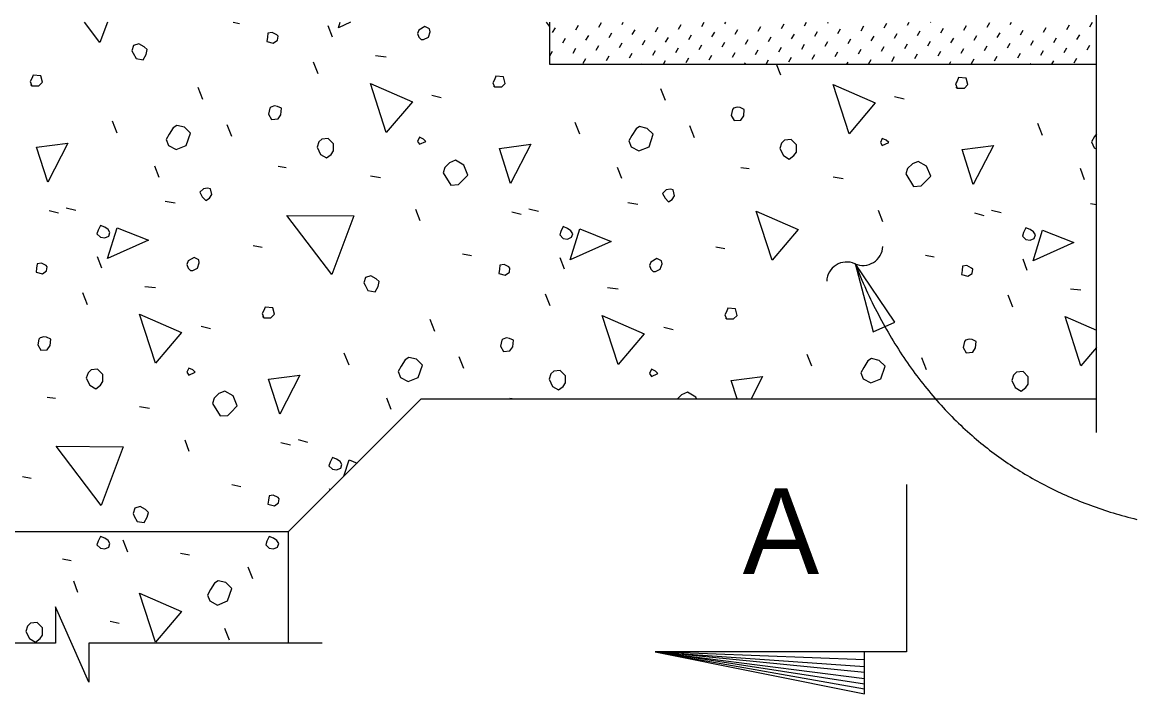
# Model space of a CAD drawing. Extents: x 120631.6 to 120706.2, y 120663.5 to 120716.4.
# Drawn here: x 120650.787 to 120654.117, y 120692.541 to 120694.546 of the extents above; entities that cross this region are included whole.
import ezdxf

# ---------------------------------------------------------------- set-up
doc = ezdxf.new("R2010")
doc.units = 0
for name, color, linetype in [('Dimension', 7, 'Continuous'), ('Miscellaneous', 7, 'Continuous'), ('TextStructures', 7, 'Continuous'), ('TrafBarrierConc', 7, 'Continuous')]:
    doc.layers.add(name, color=color, linetype=linetype)

msp = doc.modelspace()

# ---------------------------------------------------------------- linework, layer by layer
at = {"layer": 'Dimension'}
for p, q in [((120653.3036, 120692.6422), (120652.6786, 120692.6655)), ((120652.6786, 120692.6655), (120653.3036, 120692.6222)), ((120653.3036, 120692.6039), (120652.6786, 120692.6655)), ((120652.6786, 120692.6655), (120653.3036, 120692.5855)), ((120653.3036, 120692.5689), (120652.6786, 120692.6655)), ((120652.6786, 120692.6655), (120653.3036, 120692.5555))]:
    msp.add_line(p, q, dxfattribs=at)
for points in [[(120653.9962, 120693.3211), (120653.9962, 120695.4418), (120653.8928, 120695.4418), (120653.9962, 120695.4868), (120654.0995, 120695.5318), (120653.9962, 120695.5318), (120653.9962, 120696.2127)], [(120653.4286, 120693.1655), (120653.4286, 120692.6655), (120652.6786, 120692.6655), (120653.3036, 120692.5405), (120653.3036, 120692.6655)], [(120651.6828, 120692.6914), (120650.9858, 120692.6914), (120650.9858, 120692.5751), (120650.8864, 120692.8001), (120650.8864, 120692.6914), (120650.2312, 120692.6914)]]:
    msp.add_lwpolyline(points, dxfattribs=at)
msp.add_lwpolyline([(120653.2752, 120693.8252), (120653.3295, 120693.6211), (120653.3937, 120693.6504)], close=True, dxfattribs=at)
for centre, start, end in [((120653.2989, 120693.8792), 245.9128, 357.64), ((120653.2502, 120693.7704), 65.9128, 177.64)]:
    msp.add_arc(centre, 0.0596, start, end, dxfattribs=at)
msp.add_open_spline([(120653.2752, 120693.8251), (120653.5209, 120693.209), (120654.1168, 120693.0611)], degree=2, dxfattribs=at)
at = {"layer": 'Miscellaneous'}
for p, q in [((120651.417, 120694.546), (120651.4365, 120694.5421)), ((120651.7141, 120694.5015), (120651.7017, 120694.535)), ((120652.3718, 120694.5154), (120652.3799, 120694.5294)), ((120652.441, 120694.5235), (120652.4491, 120694.5375)), ((120652.5102, 120694.5316), (120652.5183, 120694.5456)), ((120652.5407, 120694.501), (120652.5488, 120694.515)), ((120652.5793, 120694.5397), (120652.583, 120694.546)), ((120652.6099, 120694.5091), (120652.618, 120694.5231)), ((120652.679, 120694.5172), (120652.6871, 120694.5312)), ((120652.7482, 120694.5253), (120652.7563, 120694.5393)), ((120652.8173, 120694.5334), (120652.8246, 120694.546)), ((120652.8479, 120694.5029), (120652.856, 120694.5169)), ((120652.8865, 120694.5415), (120652.8891, 120694.546)), ((120652.917, 120694.511), (120652.9251, 120694.525)), ((120652.9862, 120694.5191), (120652.9943, 120694.5331)), ((120653.0554, 120694.5272), (120653.0635, 120694.5412)), ((120653.1245, 120694.5353), (120653.1307, 120694.546)), ((120653.1551, 120694.5048), (120653.1632, 120694.5188)), ((120653.1937, 120694.5434), (120653.1952, 120694.546)), ((120653.2242, 120694.5129), (120653.2323, 120694.5269)), ((120653.2934, 120694.521), (120653.3015, 120694.535)), ((120653.3626, 120694.5291), (120653.3707, 120694.5431)), ((120653.4317, 120694.5372), (120653.4368, 120694.546)), ((120653.4622, 120694.5067), (120653.4703, 120694.5207)), ((120653.5009, 120694.5453), (120653.5013, 120694.546)), ((120653.5314, 120694.5148), (120653.5395, 120694.5288)), ((120653.6006, 120694.5229), (120653.6087, 120694.5369)), ((120653.6697, 120694.531), (120653.6778, 120694.545)), ((120653.7003, 120694.5004), (120653.7084, 120694.5144)), ((120653.7389, 120694.5391), (120653.7429, 120694.546)), ((120653.7694, 120694.5085), (120653.7775, 120694.5225)), ((120653.8386, 120694.5166), (120653.8467, 120694.5306)), ((120653.9078, 120694.5248), (120653.9159, 120694.5387)), ((120653.9769, 120694.5329), (120653.9845, 120694.546)), ((120652.4024, 120694.4848), (120652.4105, 120694.4988)), ((120652.4715, 120694.4929), (120652.4796, 120694.5069)), ((120652.5712, 120694.4705), (120652.5793, 120694.4845)), ((120652.6404, 120694.4786), (120652.6485, 120694.4926)), ((120652.7095, 120694.4867), (120652.7176, 120694.5007)), ((120652.7787, 120694.4948), (120652.7868, 120694.5088)), ((120652.8784, 120694.4724), (120652.8865, 120694.4864)), ((120652.9476, 120694.4805), (120652.9557, 120694.4945)), ((120653.0167, 120694.4886), (120653.0248, 120694.5026)), ((120653.0859, 120694.4967), (120653.094, 120694.5107)), ((120653.1856, 120694.4743), (120653.1937, 120694.4883)), ((120653.2548, 120694.4824), (120653.2629, 120694.4964)), ((120653.3239, 120694.4905), (120653.332, 120694.5045)), ((120653.3931, 120694.4986), (120653.4012, 120694.5126)), ((120653.4236, 120694.468), (120653.4317, 120694.482)), ((120653.4928, 120694.4761), (120653.5009, 120694.4901)), ((120653.5619, 120694.4842), (120653.57, 120694.4982)), ((120653.6311, 120694.4923), (120653.6392, 120694.5063)), ((120653.7308, 120694.4699), (120653.7389, 120694.4839)), ((120653.8, 120694.478), (120653.8081, 120694.492)), ((120653.8691, 120694.4861), (120653.8772, 120694.5001)), ((120653.9383, 120694.4942), (120653.9464, 120694.5082)), ((120652.3637, 120694.4462), (120652.3718, 120694.4602)), ((120652.4329, 120694.4543), (120652.441, 120694.4683)), ((120652.5021, 120694.4624), (120652.5102, 120694.4764)), ((120652.6017, 120694.44), (120652.6099, 120694.454)), ((120652.6709, 120694.4481), (120652.679, 120694.4621)), ((120652.7401, 120694.4562), (120652.7482, 120694.4702)), ((120652.8092, 120694.4643), (120652.8173, 120694.4783)), ((120652.8398, 120694.4337), (120652.8479, 120694.4477)), ((120652.9089, 120694.4419), (120652.917, 120694.4558)), ((120652.9781, 120694.45), (120652.9862, 120694.4639)), ((120653.0473, 120694.4581), (120653.0554, 120694.4721)), ((120653.1164, 120694.4662), (120653.1245, 120694.4802)), ((120653.147, 120694.4356), (120653.1551, 120694.4496)), ((120653.2161, 120694.4437), (120653.2242, 120694.4577)), ((120653.2853, 120694.4518), (120653.2934, 120694.4658)), ((120653.3544, 120694.4599), (120653.3626, 120694.4739)), ((120653.4541, 120694.4375), (120653.4622, 120694.4515)), ((120653.5233, 120694.4456), (120653.5314, 120694.4596)), ((120653.5925, 120694.4537), (120653.6006, 120694.4677)), ((120653.6616, 120694.4618), (120653.6697, 120694.4758)), ((120653.7613, 120694.4394), (120653.7694, 120694.4534)), ((120653.8305, 120694.4475), (120653.8386, 120694.4615)), ((120653.8997, 120694.4556), (120653.9078, 120694.4696)), ((120653.9688, 120694.4637), (120653.9769, 120694.4777)), ((120651.6717, 120694.3918), (120651.6575, 120694.4272)), ((120651.8431, 120694.4466), (120651.8749, 120694.4431)), ((120652.4634, 120694.4238), (120652.4715, 120694.4378)), ((120652.5326, 120694.4319), (120652.5407, 120694.4459)), ((120652.639, 120694.421), (120652.6404, 120694.4234)), ((120652.7034, 120694.421), (120652.7095, 120694.4315)), ((120652.7706, 120694.4256), (120652.7787, 120694.4396)), ((120652.9451, 120694.421), (120652.9476, 120694.4253)), ((120653.0095, 120694.421), (120653.0167, 120694.4334)), ((120653.054, 120694.3883), (120653.041, 120694.421)), ((120653.0778, 120694.4275), (120653.0859, 120694.4415)), ((120653.2512, 120694.421), (120653.2548, 120694.4272)), ((120653.3158, 120694.4213), (120653.3239, 120694.4353)), ((120653.385, 120694.4294), (120653.3931, 120694.4434)), ((120653.5573, 120694.421), (120653.5619, 120694.4291)), ((120653.623, 120694.4232), (120653.6311, 120694.4372)), ((120653.6922, 120694.4313), (120653.7003, 120694.4453)), ((120653.7989, 120694.421), (120653.8, 120694.4228)), ((120653.8634, 120694.421), (120653.8691, 120694.431)), ((120653.9302, 120694.4251), (120653.9383, 120694.4391)), ((120651.3269, 120694.3158), (120651.3128, 120694.3512)), ((120652.7093, 120694.3123), (120652.6952, 120694.3477)), ((120652.0111, 120694.3282), (120652.0393, 120694.3211)), ((120653.3935, 120694.3247), (120653.4217, 120694.3176)), ((120651.0706, 120694.2151), (120651.0565, 120694.2504)), ((120651.4136, 120694.2045), (120651.3994, 120694.2398)), ((120652.453, 120694.2115), (120652.4389, 120694.2469)), ((120652.796, 120694.2009), (120652.7818, 120694.2363)), ((120653.8354, 120694.208), (120653.8213, 120694.2434)), ((120651.1961, 120694.0825), (120651.1837, 120694.1161)), ((120651.5514, 120694.1161), (120651.5762, 120694.1125)), ((120651.8272, 120694.0878), (120651.8573, 120694.0825)), ((120652.5785, 120694.079), (120652.5661, 120694.1125)), ((120652.9338, 120694.1125), (120652.9586, 120694.109)), ((120653.2096, 120694.0843), (120653.2397, 120694.079)), ((120653.9609, 120694.0754), (120653.9485, 120694.109)), ((120650.8673, 120693.9835), (120650.8956, 120693.9764)), ((120650.9186, 120693.9923), (120650.9469, 120693.9853)), ((120651.2138, 120694.0118), (120651.2439, 120694.0065)), ((120651.9757, 120693.9534), (120651.9633, 120693.987)), ((120652.301, 120693.9888), (120652.3293, 120693.9817)), ((120652.5962, 120694.0082), (120652.6262, 120694.0029)), ((120653.3581, 120693.9499), (120653.3457, 120693.9835)), ((120653.6834, 120693.9853), (120653.7117, 120693.9782)), ((120653.9786, 120694.0047), (120653.9962, 120694.0016)), ((120652.2497, 120693.98), (120652.278, 120693.9729)), ((120653.6321, 120693.9764), (120653.6604, 120693.9694)), ((120651.4772, 120693.8792), (120651.5037, 120693.8739)), ((120652.103, 120693.8544), (120652.1295, 120693.8491)), ((120652.8596, 120693.8757), (120652.8861, 120693.8704)), ((120653.4854, 120693.8509), (120653.5119, 120693.8456)), ((120651.0246, 120693.812), (120651.0123, 120693.8456)), ((120652.407, 120693.8085), (120652.3947, 120693.8421)), ((120653.7894, 120693.8049), (120653.7771, 120693.8385)), ((120651.1537, 120693.7572), (120651.1855, 120693.7537)), ((120652.5361, 120693.7537), (120652.5679, 120693.7501)), ((120653.9185, 120693.7501), (120653.9503, 120693.7466)), ((120650.9822, 120693.7024), (120650.9681, 120693.7378)), ((120652.3646, 120693.6989), (120652.3505, 120693.7342)), ((120653.747, 120693.6953), (120653.7329, 120693.7307)), ((120652.0199, 120693.6229), (120652.0058, 120693.6582)), ((120651.3216, 120693.6388), (120651.3499, 120693.6317)), ((120652.704, 120693.6352), (120652.7323, 120693.6282)), ((120651.7636, 120693.5221), (120651.7494, 120693.5575)), ((120653.146, 120693.5186), (120653.1318, 120693.5539)), ((120652.1065, 120693.5115), (120652.0924, 120693.5469)), ((120653.4889, 120693.508), (120653.4748, 120693.5433)), ((120650.862, 120693.4266), (120650.8868, 120693.4231)), ((120651.8891, 120693.3895), (120651.8767, 120693.4231)), ((120652.2444, 120693.4231), (120652.2591, 120693.421)), ((120651.1378, 120693.3984), (120651.1678, 120693.3931)), ((120651.2863, 120693.264), (120651.2739, 120693.2976)), ((120651.5603, 120693.2905), (120651.5886, 120693.2835)), ((120651.6115, 120693.2994), (120651.6398, 120693.2923)), ((120650.7878, 120693.1898), (120650.8143, 120693.1845)), ((120651.4136, 120693.165), (120651.4401, 120693.1597)), ((120651.7068, 120693.1484), (120651.7052, 120693.1526)), ((120651.1032, 120692.9637), (120651.0891, 120692.9991)), ((120651.2604, 120692.9603), (120651.2869, 120692.955)), ((120650.9072, 120692.9436), (120650.9337, 120692.9383)), ((120651.4765, 120692.8837), (120651.4623, 120692.919)), ((120650.9536, 120692.8428), (120650.9412, 120692.8764)), ((120651.0504, 120692.757), (120651.077, 120692.7517)), ((120651.4065, 120692.7004), (120651.3924, 120692.7357))]:
    msp.add_line(p, q, dxfattribs=at)
for points in [[(120651.0193, 120694.4855), (120650.9734, 120694.546)], [(120651.0419, 120694.546), (120651.0193, 120694.4855)], [(120651.5179, 120694.4891), (120651.5373, 120694.4838), (120651.5497, 120694.4926), (120651.5514, 120694.505), (120651.5479, 120694.5085), (120651.5338, 120694.5156), (120651.5214, 120694.5138), (120651.5196, 120694.5015), (120651.5179, 120694.4891)], [(120651.7318, 120694.5297), (120651.7368, 120694.546)], [(120651.768, 120694.546), (120651.7318, 120694.5297)], [(120651.9792, 120694.4944), (120651.9863, 120694.4944), (120652.0005, 120694.5015), (120652.0058, 120694.5174), (120652.004, 120694.5262), (120651.9899, 120694.5333), (120651.9722, 120694.5227), (120651.9686, 120694.5121), (120651.9722, 120694.5015), (120651.9792, 120694.4944)], [(120652.362, 120694.5343), (120652.3531, 120694.546)], [(120651.1183, 120694.4537), (120651.1272, 120694.4378), (120651.1484, 120694.4343), (120651.1572, 120694.4502), (120651.1608, 120694.4643), (120651.1519, 120694.4732), (120651.136, 120694.482), (120651.1201, 120694.4767), (120651.1148, 120694.4608), (120651.1183, 120694.4537)], [(120650.8161, 120694.3565), (120650.8373, 120694.3565), (120650.8479, 120694.3671), (120650.8426, 120694.3865), (120650.8196, 120694.3883), (120650.8161, 120694.3777), (120650.8107, 120694.3689), (120650.8161, 120694.3565), (120650.8125, 120694.36)], [(120652.1984, 120694.353), (120652.2197, 120694.353), (120652.2303, 120694.3636), (120652.225, 120694.383), (120652.202, 120694.3848), (120652.1984, 120694.3742), (120652.1931, 120694.3653), (120652.1984, 120694.353), (120652.1949, 120694.3565)], [(120653.5808, 120694.3494), (120653.6021, 120694.3494), (120653.6127, 120694.36), (120653.6074, 120694.3795), (120653.5844, 120694.3812), (120653.5808, 120694.3706), (120653.5755, 120694.3618), (120653.5808, 120694.3494), (120653.5773, 120694.353)], [(120651.8749, 120694.2168), (120651.8272, 120694.3636), (120651.9527, 120694.3088), (120651.8749, 120694.2168)], [(120653.2573, 120694.2133), (120653.2096, 120694.36), (120653.3351, 120694.3052), (120653.2573, 120694.2133)], [(120651.5232, 120694.2716), (120651.532, 120694.2557), (120651.5514, 120694.2575), (120651.5603, 120694.2699), (120651.5621, 120694.2893), (120651.5497, 120694.2946), (120651.5408, 120694.2964), (120651.5302, 120694.2929), (120651.5267, 120694.2893), (120651.5232, 120694.2716)], [(120652.9056, 120694.2681), (120652.9144, 120694.2522), (120652.9338, 120694.254), (120652.9427, 120694.2663), (120652.9444, 120694.2858), (120652.9321, 120694.2911), (120652.9232, 120694.2929), (120652.9126, 120694.2893), (120652.9091, 120694.2858), (120652.9056, 120694.2681)], [(120651.2244, 120694.1779), (120651.2474, 120694.1656), (120651.2774, 120694.1779), (120651.2898, 120694.2151), (120651.2721, 120694.2327), (120651.2492, 120694.2381), (120651.2385, 120694.231), (120651.2262, 120694.2115), (120651.2173, 120694.1956), (120651.2244, 120694.1779)], [(120652.6068, 120694.1744), (120652.6298, 120694.162), (120652.6598, 120694.1744), (120652.6722, 120694.2115), (120652.6545, 120694.2292), (120652.6315, 120694.2345), (120652.6209, 120694.2274), (120652.6086, 120694.208), (120652.5997, 120694.1921), (120652.6068, 120694.1744)], [(120650.8638, 120694.0683), (120650.8302, 120694.1726), (120650.9239, 120694.185), (120650.8638, 120694.0683)], [(120651.6681, 120694.1726), (120651.6787, 120694.1514), (120651.6964, 120694.1408), (120651.7105, 120694.1514), (120651.7176, 120694.162), (120651.7176, 120694.1833), (120651.7017, 120694.1992), (120651.6823, 120694.1974), (120651.6734, 120694.1886), (120651.6681, 120694.1726)], [(120651.9739, 120694.1815), (120651.9934, 120694.1903), (120651.9863, 120694.1974), (120651.9739, 120694.2027), (120651.9686, 120694.1903), (120651.9739, 120694.1815)], [(120652.2462, 120694.0648), (120652.2126, 120694.1691), (120652.3063, 120694.1815), (120652.2462, 120694.0648)], [(120653.0505, 120694.1691), (120653.0611, 120694.1479), (120653.0788, 120694.1373), (120653.0929, 120694.1479), (120653.1, 120694.1585), (120653.1, 120694.1797), (120653.0841, 120694.1956), (120653.0647, 120694.1939), (120653.0558, 120694.185), (120653.0505, 120694.1691)], [(120653.3563, 120694.1779), (120653.3758, 120694.1868), (120653.3687, 120694.1939), (120653.3563, 120694.1992), (120653.351, 120694.1868), (120653.3563, 120694.1779)], [(120653.9962, 120694.2126), (120653.991, 120694.2045), (120653.9821, 120694.1886), (120653.9892, 120694.1709)], [(120653.6286, 120694.0613), (120653.595, 120694.1656), (120653.6887, 120694.1779), (120653.6286, 120694.0613)], [(120653.9892, 120694.1709), (120653.9962, 120694.1671)], [(120652.0447, 120694.0966), (120652.0676, 120694.0595), (120652.0906, 120694.0613), (120652.0995, 120694.0701), (120652.1189, 120694.0896), (120652.1065, 120694.1196), (120652.0818, 120694.1338), (120652.0641, 120694.1267), (120652.05, 120694.1125), (120652.0447, 120694.0966)], [(120653.427, 120694.0931), (120653.45, 120694.056), (120653.473, 120694.0577), (120653.4818, 120694.0666), (120653.5013, 120694.086), (120653.4889, 120694.1161), (120653.4642, 120694.1302), (120653.4465, 120694.1231), (120653.4323, 120694.109), (120653.427, 120694.0931)], [(120651.3252, 120694.0242), (120651.3358, 120694.0135), (120651.3464, 120694.0206), (120651.3535, 120694.0312), (120651.3499, 120694.0489), (120651.3411, 120694.0507), (120651.3287, 120694.0489), (120651.3181, 120694.0383), (120651.3252, 120694.0242)], [(120652.7076, 120694.0206), (120652.7182, 120694.01), (120652.7288, 120694.0171), (120652.7358, 120694.0277), (120652.7323, 120694.0454), (120652.7235, 120694.0471), (120652.7111, 120694.0454), (120652.7005, 120694.0348), (120652.7076, 120694.0206)], [(120653.028, 120693.8353), (120652.9803, 120693.982), (120653.1058, 120693.9272), (120653.028, 120693.8353)], [(120651.7123, 120693.7926), (120651.578, 120693.9694), (120651.7777, 120693.9676), (120651.7123, 120693.7926)], [(120651.0211, 120693.9039), (120651.0335, 120693.9022), (120651.0459, 120693.9075), (120651.0494, 120693.9181), (120651.0441, 120693.9269), (120651.0335, 120693.934), (120651.0211, 120693.9393), (120651.014, 120693.9252), (120651.0105, 120693.9146), (120651.0211, 120693.9039)], [(120651.0423, 120693.8403), (120651.0706, 120693.9322), (120651.1643, 120693.8951), (120651.0423, 120693.8403)], [(120652.4035, 120693.9004), (120652.4159, 120693.8986), (120652.4283, 120693.9039), (120652.4318, 120693.9146), (120652.4265, 120693.9234), (120652.4159, 120693.9305), (120652.4035, 120693.9358), (120652.3964, 120693.9216), (120652.3929, 120693.911), (120652.4035, 120693.9004)], [(120652.4247, 120693.8368), (120652.453, 120693.9287), (120652.5467, 120693.8916), (120652.4247, 120693.8368)], [(120653.7859, 120693.8969), (120653.7983, 120693.8951), (120653.8107, 120693.9004), (120653.8142, 120693.911), (120653.8089, 120693.9199), (120653.7983, 120693.9269), (120653.7859, 120693.9322), (120653.7788, 120693.9181), (120653.7753, 120693.9075), (120653.7859, 120693.8969)], [(120653.8071, 120693.8332), (120653.8354, 120693.9252), (120653.9291, 120693.888), (120653.8071, 120693.8332)], [(120650.8284, 120693.7996), (120650.8479, 120693.7943), (120650.8602, 120693.8032), (120650.862, 120693.8156), (120650.8585, 120693.8191), (120650.8443, 120693.8262), (120650.832, 120693.8244), (120650.8302, 120693.812), (120650.8284, 120693.7996)], [(120651.2898, 120693.8049), (120651.2969, 120693.8049), (120651.311, 120693.812), (120651.3163, 120693.8279), (120651.3146, 120693.8368), (120651.3004, 120693.8438), (120651.2827, 120693.8332), (120651.2792, 120693.8226), (120651.2827, 120693.812), (120651.2898, 120693.8049)], [(120652.2108, 120693.7961), (120652.2303, 120693.7908), (120652.2426, 120693.7996), (120652.2444, 120693.812), (120652.2409, 120693.8156), (120652.2267, 120693.8226), (120652.2144, 120693.8209), (120652.2126, 120693.8085), (120652.2108, 120693.7961)], [(120652.6722, 120693.8014), (120652.6793, 120693.8014), (120652.6934, 120693.8085), (120652.6987, 120693.8244), (120652.697, 120693.8332), (120652.6828, 120693.8403), (120652.6651, 120693.8297), (120652.6616, 120693.8191), (120652.6651, 120693.8085), (120652.6722, 120693.8014)], [(120653.5932, 120693.7926), (120653.6127, 120693.7873), (120653.625, 120693.7961), (120653.6268, 120693.8085), (120653.6233, 120693.812), (120653.6091, 120693.8191), (120653.5968, 120693.8173), (120653.595, 120693.8049), (120653.5932, 120693.7926)], [(120651.8113, 120693.7608), (120651.8201, 120693.7448), (120651.8414, 120693.7413), (120651.8502, 120693.7572), (120651.8537, 120693.7714), (120651.8449, 120693.7802), (120651.829, 120693.789), (120651.8131, 120693.7837), (120651.8078, 120693.7678), (120651.8113, 120693.7608)], [(120651.509, 120693.6635), (120651.5302, 120693.6635), (120651.5408, 120693.6741), (120651.5355, 120693.6936), (120651.5126, 120693.6953), (120651.509, 120693.6847), (120651.5037, 120693.6759), (120651.509, 120693.6635), (120651.5055, 120693.6671)], [(120652.8914, 120693.66), (120652.9126, 120693.66), (120652.9232, 120693.6706), (120652.9179, 120693.69), (120652.8949, 120693.6918), (120652.8914, 120693.6812), (120652.8861, 120693.6724), (120652.8914, 120693.66), (120652.8879, 120693.6635)], [(120651.1855, 120693.5274), (120651.1378, 120693.6741), (120651.2633, 120693.6193), (120651.1855, 120693.5274)], [(120652.5679, 120693.5239), (120652.5202, 120693.6706), (120652.6457, 120693.6158), (120652.5679, 120693.5239)], [(120653.9503, 120693.5203), (120653.9026, 120693.6671), (120653.9962, 120693.6262)], [(120650.8337, 120693.5822), (120650.8426, 120693.5663), (120650.862, 120693.5681), (120650.8709, 120693.5804), (120650.8726, 120693.5999), (120650.8602, 120693.6052), (120650.8514, 120693.607), (120650.8408, 120693.6034), (120650.8373, 120693.5999), (120650.8337, 120693.5822)], [(120652.2161, 120693.5787), (120652.225, 120693.5628), (120652.2444, 120693.5645), (120652.2532, 120693.5769), (120652.255, 120693.5964), (120652.2426, 120693.6017), (120652.2338, 120693.6034), (120652.2232, 120693.5999), (120652.2197, 120693.5964), (120652.2161, 120693.5787)], [(120653.5985, 120693.5751), (120653.6074, 120693.5592), (120653.6268, 120693.561), (120653.6356, 120693.5734), (120653.6374, 120693.5928), (120653.625, 120693.5981), (120653.6162, 120693.5999), (120653.6056, 120693.5964), (120653.6021, 120693.5928), (120653.5985, 120693.5751)], [(120653.9962, 120693.5745), (120653.9503, 120693.5203)], [(120651.9174, 120693.485), (120651.9404, 120693.4726), (120651.9704, 120693.485), (120651.9828, 120693.5221), (120651.9651, 120693.5398), (120651.9421, 120693.5451), (120651.9315, 120693.538), (120651.9191, 120693.5186), (120651.9103, 120693.5027), (120651.9174, 120693.485)], [(120653.2998, 120693.4814), (120653.3227, 120693.4691), (120653.3528, 120693.4814), (120653.3652, 120693.5186), (120653.3475, 120693.5362), (120653.3245, 120693.5416), (120653.3139, 120693.5345), (120653.3015, 120693.515), (120653.2927, 120693.4991), (120653.2998, 120693.4814)], [(120650.9787, 120693.4832), (120650.9893, 120693.462), (120651.007, 120693.4514), (120651.0211, 120693.462), (120651.0282, 120693.4726), (120651.0282, 120693.4938), (120651.0123, 120693.5097), (120650.9928, 120693.508), (120650.984, 120693.4991), (120650.9787, 120693.4832)], [(120651.2845, 120693.4921), (120651.304, 120693.5009), (120651.2969, 120693.508), (120651.2845, 120693.5133), (120651.2792, 120693.5009), (120651.2845, 120693.4921)], [(120651.5567, 120693.3754), (120651.5232, 120693.4797), (120651.6169, 120693.4921), (120651.5567, 120693.3754)], [(120652.3611, 120693.4797), (120652.3717, 120693.4585), (120652.3894, 120693.4479), (120652.4035, 120693.4585), (120652.4106, 120693.4691), (120652.4106, 120693.4903), (120652.3947, 120693.5062), (120652.3752, 120693.5044), (120652.3664, 120693.4956), (120652.3611, 120693.4797)], [(120652.6669, 120693.4885), (120652.6864, 120693.4974), (120652.6793, 120693.5044), (120652.6669, 120693.5097), (120652.6616, 120693.4974), (120652.6669, 120693.4885)], [(120652.9233, 120693.421), (120652.9056, 120693.4761), (120652.9992, 120693.4885), (120652.9645, 120693.421)], [(120653.7435, 120693.4761), (120653.7541, 120693.4549), (120653.7718, 120693.4443), (120653.7859, 120693.4549), (120653.793, 120693.4655), (120653.793, 120693.4868), (120653.7771, 120693.5027), (120653.7576, 120693.5009), (120653.7488, 120693.4921), (120653.7435, 120693.4761)], [(120651.3552, 120693.4072), (120651.3782, 120693.3701), (120651.4012, 120693.3718), (120651.41, 120693.3807), (120651.4295, 120693.4001), (120651.4171, 120693.4302), (120651.3923, 120693.4443), (120651.3747, 120693.4373), (120651.3605, 120693.4231), (120651.3552, 120693.4072)], [(120652.8018, 120693.421), (120652.7995, 120693.4266), (120652.7747, 120693.4408), (120652.7571, 120693.4337), (120652.7444, 120693.421)], [(120651.0229, 120693.1031), (120650.8885, 120693.2799), (120651.0883, 120693.2782), (120651.0229, 120693.1031)], [(120651.7141, 120693.211), (120651.7265, 120693.2092), (120651.7388, 120693.2145), (120651.7424, 120693.2251), (120651.7371, 120693.234), (120651.7265, 120693.241), (120651.7141, 120693.2463), (120651.707, 120693.2322), (120651.7035, 120693.2216), (120651.7141, 120693.211)], [(120651.7485, 120693.1901), (120651.7636, 120693.2393), (120651.7879, 120693.2296)], [(120651.5214, 120693.1067), (120651.5408, 120693.1014), (120651.5532, 120693.1102), (120651.555, 120693.1226), (120651.5514, 120693.1261), (120651.5373, 120693.1332), (120651.5249, 120693.1314), (120651.5232, 120693.1191), (120651.5214, 120693.1067)], [(120651.1219, 120693.0713), (120651.1307, 120693.0554), (120651.1519, 120693.0519), (120651.1608, 120693.0678), (120651.1643, 120693.0819), (120651.1555, 120693.0908), (120651.1396, 120693.0996), (120651.1236, 120693.0943), (120651.1183, 120693.0784), (120651.1219, 120693.0713)], [(120651.0211, 120692.975), (120651.0335, 120692.9732), (120651.0459, 120692.9786), (120651.0494, 120692.9892), (120651.0441, 120692.998), (120651.0335, 120693.0051), (120651.0211, 120693.0104), (120651.014, 120692.9962), (120651.0105, 120692.9856), (120651.0211, 120692.975)], [(120651.5253, 120692.975), (120651.5377, 120692.9732), (120651.55, 120692.9786), (120651.5536, 120692.9892), (120651.5483, 120692.998), (120651.5377, 120693.0051), (120651.5253, 120693.0104), (120651.5182, 120692.9962), (120651.5147, 120692.9856), (120651.5253, 120692.975)], [(120651.3479, 120692.8177), (120651.3709, 120692.8053), (120651.4009, 120692.8177), (120651.4133, 120692.8548), (120651.3956, 120692.8725), (120651.3727, 120692.8778), (120651.362, 120692.8707), (120651.3497, 120692.8513), (120651.3408, 120692.8353), (120651.3479, 120692.8177)], [(120651.1855, 120692.6946), (120651.1378, 120692.8413), (120651.2633, 120692.7865), (120651.1855, 120692.6946)], [(120650.7981, 120692.7263), (120650.8087, 120692.7051), (120650.8264, 120692.6945), (120650.8405, 120692.7051), (120650.8476, 120692.7157), (120650.8476, 120692.7369), (120650.8317, 120692.7528), (120650.8123, 120692.751), (120650.8034, 120692.7422), (120650.7981, 120692.7263)]]:
    msp.add_lwpolyline(points, dxfattribs=at)
at = {"layer": 'TrafBarrierConc'}
for p, q in [((120652.362, 120694.546), (120652.362, 120694.421)), ((120652.362, 120694.421), (120653.9962, 120694.421)), ((120651.582, 120693.0237), (120651.9793, 120693.4211)), ((120651.9793, 120693.4211), (120653.9962, 120693.4211)), ((120651.582, 120693.0237), (120650.362, 120693.0237)), ((120651.582, 120693.0237), (120651.582, 120692.6914))]:
    msp.add_line(p, q, dxfattribs=at)

# ---------------------------------------------------------------- texts
at = {"layer": 'TextStructures'}
msp.add_text('A', height=0.256, dxfattribs=at).set_placement((120652.9397, 120692.8984))

doc.saveas('drawing.dxf')
